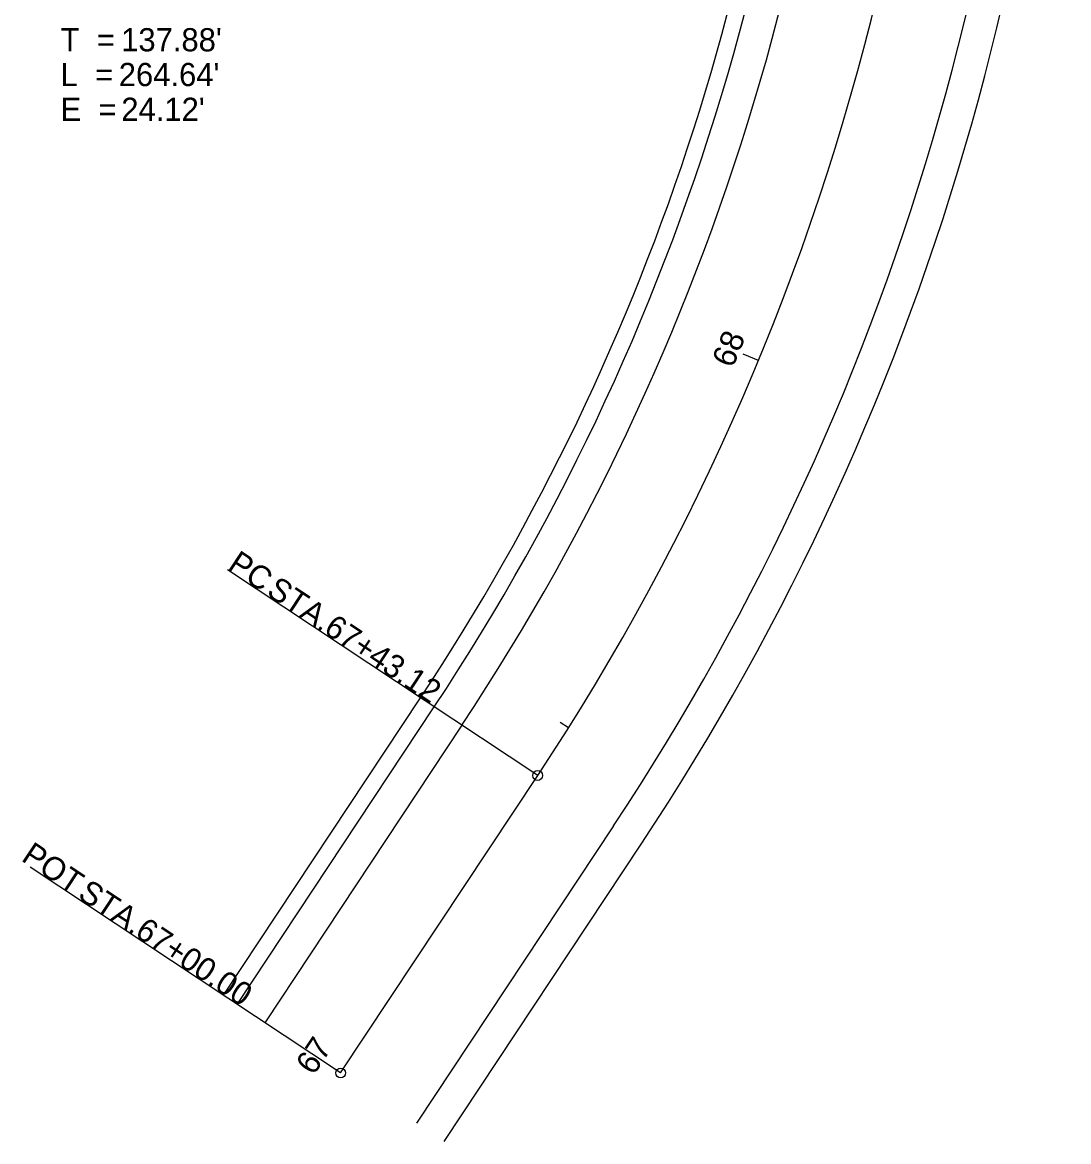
# Model space of a CAD drawing. Extents: x 27625 to 127752, y 6088 to 302357.
# Drawn here: x 127622.9 to 127749.3, y 301766.7 to 301901.9 of the extents above; entities that cross this region are included whole.
import ezdxf

# ---------------------------------------------------------------- set-up
doc = ezdxf.new("R2010")
doc.units = 0
for name, color, linetype in [('DR_X_Cells', 7, 'Continuous'), ('RS_Raster2', 7, 'Continuous'), ('SC_Scratch13', 7, 'Continuous'), ('SV_P_Control_Cells_Set', 7, 'Continuous'), ('SV_X_Mon_Cells_Found', 7, 'Continuous'), ('SV_X_Random_Point', 7, 'Continuous'), ('UT_X_Telecom_Cells', 7, 'Continuous')]:
    doc.layers.add(name, color=color, linetype=linetype)

msp = doc.modelspace()

# ---------------------------------------------------------------- linework, layer by layer
at = {"layer": 'DR_X_Cells'}
for p, q in [((127711.84, 301861.03), (127709.99, 301861.79)), ((127688.89, 301816.67), (127687.87, 301817.31)), ((127661.33, 301774.96), (127659.66, 301776.06))]:
    msp.add_line(p, q, dxfattribs=at)
at = {"layer": 'SC_Scratch13'}
msp.add_line((127661.33, 301774.96), (127685.15, 301810.9), dxfattribs=at)
msp.add_arc((127439.05, 301974.06), 295.28, 326.4564, 6.6714, dxfattribs=at)
at = {"layer": 'SV_P_Control_Cells_Set'}
for p in [(127647.16, 301784.35), (127670.98, 301820.29)]:
    msp.add_line(p, (127670.98, 301820.29), dxfattribs=at)
msp.add_arc((127439.07, 301974.05), 278.26, 326.4555, 357.95, dxfattribs=at)
at = {"layer": 'SV_X_Mon_Cells_Found'}
for p, q in [((127685.15, 301810.9), (127647.65, 301835.76)), ((127661.33, 301774.96), (127623.82, 301799.82))]:
    msp.add_line(p, q, dxfattribs=at)
for centre in [(127685.15, 301810.9), (127661.33, 301774.96)]:
    msp.add_circle(centre, 0.6, dxfattribs=at)
at = {"layer": 'SV_X_Random_Point'}
for p, q in [((127648.82, 301783.24), (127672.65, 301819.18)), ((127673.83, 301766.67), (127697.66, 301802.61))]:
    msp.add_line(p, q, dxfattribs=at)
for radius, end in [(310.28, 1.9632), (280.28, 1.0227)]:
    msp.add_arc((127439.05, 301974.06), radius, 326.4564, end, dxfattribs=at)
at = {"layer": 'UT_X_Telecom_Cells'}
for p, q in [((127675.99, 301816.97), (127652.16, 301781.03)), ((127694.32, 301804.82), (127670.5, 301768.88))]:
    msp.add_line(p, q, dxfattribs=at)
for radius, end in [(306.28, 1.8486), (284.28, 1.1597)]:
    msp.add_arc((127439.05, 301974.06), radius, 326.4564, end, dxfattribs=at)

# ---------------------------------------------------------------- texts
at = {"layer": 'DR_X_Cells'}
for s, rotation, p in [('68', 67.4935, (127708.71, 301860.02)), ('67', 56.4564, (127658.07, 301774.57))]:
    msp.add_text(s, height=2.8, rotation=rotation, dxfattribs=at).set_placement(p)
at = {"layer": 'RS_Raster2'}
for s, p in [('T  = ', (127627.48, 301898.38)), ("137.88'", (127634.8, 301898.38)), ('L  = ', (127627.48, 301894.18)), ("264.64'", (127634.51, 301894.18)), ('E  = ', (127627.48, 301889.98)), ("24.12'", (127634.82, 301889.98))]:
    msp.add_text(s, height=2.8, dxfattribs=at).set_placement(p)
at = {"layer": 'SV_X_Mon_Cells_Found'}
for s, p in [('PC', (127647.53, 301835.88)), (' STA. ', (127651.37, 301833.34)), ('67+43.12', (127659.14, 301828.19)), ('POT', (127622.6, 301800.67)), (' STA. ', (127628.55, 301796.73)), ('67+00.00', (127636.32, 301791.58))]:
    msp.add_text(s, height=2.8, rotation=326.4564, dxfattribs=at).set_placement(p)

doc.saveas('drawing.dxf')
